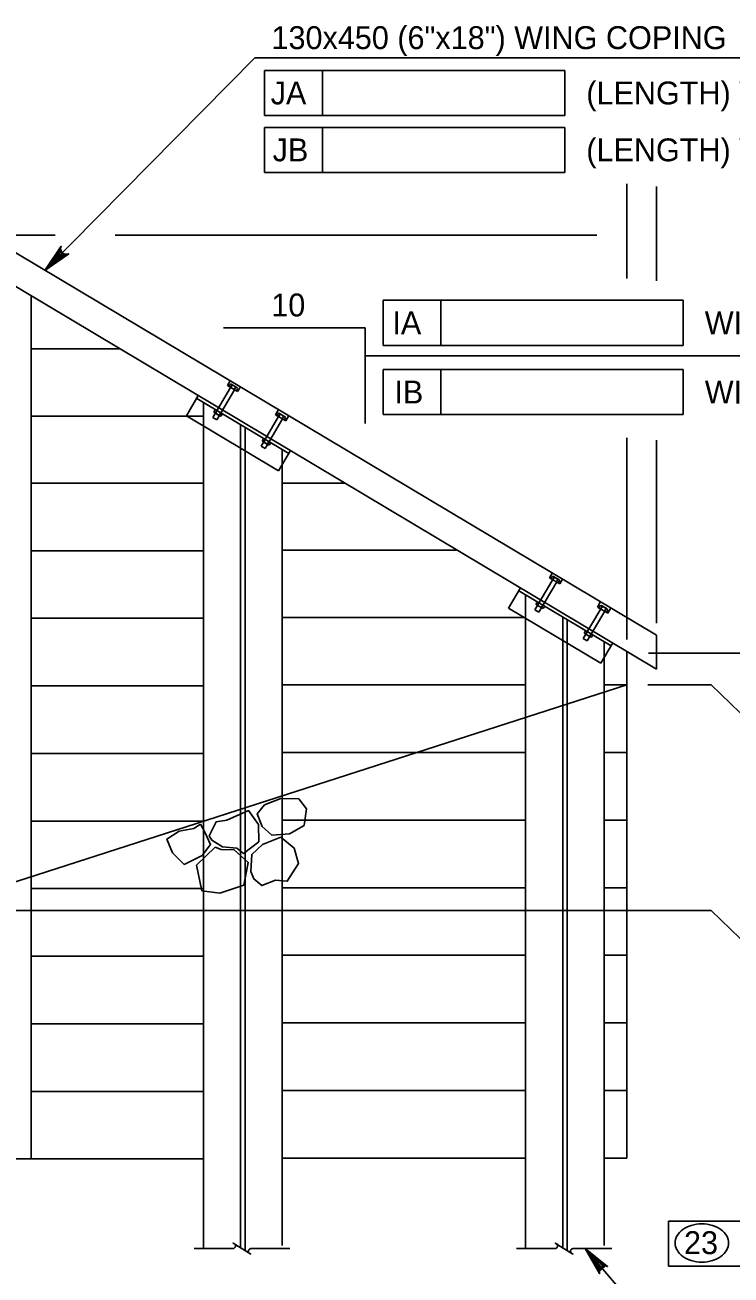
# Model space of a CAD drawing. Extents: x 635440 to 640306, y 296653 to 298484.
# Drawn here: x 639693.2 to 639785.8, y 296736.5 to 296900.4 of the extents above; entities that cross this region are included whole.
import ezdxf

# ---------------------------------------------------------------- set-up
doc = ezdxf.new("R2010")
doc.units = 0
for name, color, linetype in [('3', 7, 'Continuous'), ('4', 7, 'Continuous'), ('5', 7, 'Continuous'), ('8', 7, 'Continuous')]:
    doc.layers.add(name, color=color, linetype=linetype)

# ---------------------------------------------------------------- blocks, each defined once
blk = doc.blocks.new('ROCK')
at = {"layer": '4'}
for points in [[(2.36725, 1.088), (2.2065, 0.82625), (2.378625, 0.506625), (2.66975, 0.3095), (3.128875, 0.403375), (3.48475, 0.6775), (3.4915, 1.123375), (3.25625, 1.36725), (2.783625, 1.308375)], [(1.10175, -0.02725), (1.4015, -0.159125), (1.78825, -0.148875), (1.980875, -0.266), (2.343375, 0.09475), (2.27875, 0.5505), (1.969375, 0.883), (1.4225, 0.553625), (1.152875, 0.479), (1.0105, 0.082)], [(0.74675, 0.359875), (0.882, 0.16), (1.072875, -0.144), (0.892, -0.457375), (0.448125, -0.758625), (0.1, -0.49325), (-0.095, -0.146375), (0.202875, 0.1025), (0.579125, 0.219875)], [(2.231375, -0.71725), (2.2025, -0.266375), (2.45475, 0.037125), (2.9085, 0.28875), (3.2995, 0.047625), (3.46875, -0.344), (3.231625, -0.855), (2.92, -0.860375), (2.5765, -1.054625), (2.340375, -0.904375)], [(1.2085, -0.192875), (0.778375, -0.737625), (1.008375, -1.391375), (1.48725, -1.396875), (2.09825, -1.106625), (2.133375, -0.486375), (1.723125, -0.203375), (1.37425, -0.239875)]]:
    blk.add_lwpolyline(points, close=True, dxfattribs=at)

msp = doc.modelspace()

# ---------------------------------------------------------------- linework, layer by layer
at = {"layer": '3'}
for p, q in [((639688.15, 296872.79), (639776.08, 296820.36)), ((639688.15, 296868.36), (639776.08, 296815.93)), ((639694.03, 296788.7), (639694.03, 296864.85)), ((639705.71, 296857.89), (639694.03, 296857.89)), ((639717.86, 296848.92), (639720.18, 296852.86)), ((639719.77, 296853.1), (639720.14, 296853.72)), ((639721.12, 296852.3), (639719.77, 296853.1)), ((639719.97, 296852.98), (639720.13, 296853.25)), ((639720.36, 296853.11), (639720.2, 296852.85)), ((639720.29, 296853.27), (639721.01, 296852.85)), ((639720.84, 296852.84), (639720.68, 296852.57)), ((639720.92, 296852.42), (639721.08, 296852.69)), ((639721.12, 296852.3), (639721.49, 296852.92)), ((639714.39, 296849.14), (639715.96, 296851.78)), ((639718.39, 296848.61), (639720.71, 296852.54)), ((639718.19, 296849.96), (639718.03, 296849.68)), ((639718.09, 296849.53), (639718.81, 296849.11)), ((639718.26, 296849.55), (639718.42, 296849.82)), ((639718.73, 296849.27), (639718.89, 296849.54)), ((639719.14, 296849.4), (639718.97, 296849.13)), ((639726.07, 296849.27), (639726.44, 296849.89)), ((639726.27, 296849.15), (639726.44, 296849.43)), ((639726.59, 296849.45), (639727.31, 296849.02)), ((639714.45, 296849.1), (639694.03, 296849.1)), ((639714.39, 296849.14), (639726.49, 296841.92)), ((639716.63, 296847.8), (639716.63, 296794.57)), ((639718.39, 296848.61), (639717.86, 296848.92)), ((639724.19, 296845.15), (639726.48, 296849.03)), ((639724.72, 296844.84), (639727.01, 296848.72)), ((639727.42, 296848.48), (639726.07, 296849.27)), ((639726.66, 296849.29), (639726.5, 296849.02)), ((639727.14, 296849.01), (639726.98, 296848.74)), ((639727.22, 296848.59), (639727.38, 296848.87)), ((639727.42, 296848.48), (639727.79, 296849.09)), ((639724.52, 296846.18), (639724.36, 296845.91)), ((639724.72, 296844.84), (639724.19, 296845.15)), ((639724.42, 296845.76), (639725.14, 296845.34)), ((639724.59, 296845.78), (639724.75, 296846.05)), ((639725.06, 296845.5), (639725.22, 296845.77)), ((639725.47, 296845.63), (639725.31, 296845.35)), ((639726.48, 296841.92), (639728.06, 296844.57)), ((639726.96, 296842.73), (639726.96, 296799.31)), ((639716.63, 296840.31), (639694.03, 296840.31)), ((639735.23, 296840.29), (639726.96, 296840.29)), ((639726.96, 296834.03), (639726.96, 296829.34)), ((639716.63, 296831.45), (639694.03, 296831.45)), ((639749.97, 296831.5), (639726.96, 296831.5)), ((639762.04, 296827.9), (639762.4, 296828.52)), ((639762.23, 296827.78), (639762.4, 296828.05)), ((639762.56, 296828.07), (639763.28, 296827.65)), ((639756.65, 296823.94), (639758.22, 296826.58)), ((639760.12, 296823.72), (639762.45, 296827.66)), ((639760.65, 296823.41), (639762.98, 296827.35)), ((639763.38, 296827.1), (639762.04, 296827.9)), ((639762.62, 296827.91), (639762.46, 296827.65)), ((639763.1, 296827.64), (639762.94, 296827.37)), ((639763.19, 296827.22), (639763.34, 296827.49)), ((639763.38, 296827.1), (639763.75, 296827.72)), ((639756.65, 296823.94), (639768.75, 296816.72)), ((639760.65, 296823.41), (639760.12, 296823.72)), ((639760.45, 296824.76), (639760.29, 296824.49)), ((639760.35, 296824.34), (639761.07, 296823.91)), ((639760.52, 296824.35), (639760.68, 296824.62)), ((639760.99, 296824.07), (639761.15, 296824.34)), ((639761.4, 296824.2), (639761.24, 296823.93)), ((639766.45, 296819.95), (639768.75, 296823.83)), ((639766.98, 296819.64), (639769.28, 296823.52)), ((639768.34, 296824.07), (639768.7, 296824.69)), ((639769.69, 296823.28), (639768.34, 296824.07)), ((639768.54, 296823.95), (639768.7, 296824.23)), ((639768.92, 296824.09), (639768.76, 296823.82)), ((639768.86, 296824.25), (639769.58, 296823.82)), ((639769.4, 296823.81), (639769.24, 296823.54)), ((639769.49, 296823.4), (639769.64, 296823.67)), ((639769.69, 296823.28), (639770.05, 296823.89)), ((639716.63, 296822.59), (639694.03, 296822.59)), ((639758.89, 296822.71), (639726.96, 296822.71)), ((639758.89, 296822.6), (639758.89, 296809.58)), ((639766.98, 296819.64), (639766.45, 296819.95)), ((639766.78, 296820.98), (639766.62, 296820.71)), ((639766.68, 296820.56), (639767.4, 296820.14)), ((639766.85, 296820.58), (639767.01, 296820.85)), ((639767.32, 296820.3), (639767.48, 296820.57)), ((639767.73, 296820.43), (639767.57, 296820.15)), ((639776.08, 296820.36), (639776.08, 296815.93)), ((639768.75, 296816.72), (639770.32, 296819.37)), ((639772.18, 296818.26), (639772.18, 296813.85)), ((639769.22, 296817.53), (639769.22, 296812.95)), ((639772.18, 296813.85), (639681.37, 296784.63)), ((639716.63, 296813.73), (639694.03, 296813.73)), ((639758.89, 296813.85), (639726.96, 296813.85)), ((639772.18, 296813.85), (639769.22, 296813.85)), ((639772.18, 296813.85), (639772.18, 296751.84)), ((639769.22, 296813.02), (639769.22, 296740.39)), ((639758.89, 296809.58), (639758.89, 296740.11)), ((639716.63, 296804.87), (639694.03, 296804.87)), ((639744.65, 296804.99), (639726.96, 296804.99)), ((639758.89, 296804.99), (639744.65, 296804.99)), ((639772.18, 296804.99), (639769.22, 296804.99)), ((639726.96, 296799.31), (639726.96, 296740.39)), ((639716.63, 296796.02), (639694.03, 296796.02)), ((639758.89, 296796.14), (639726.96, 296796.14)), ((639772.18, 296796.14), (639769.22, 296796.14)), ((639716.63, 296794.57), (639716.63, 296740.11)), ((639694.03, 296751.72), (639694.03, 296788.7)), ((639716.63, 296787.16), (639694.03, 296787.16)), ((639758.89, 296787.28), (639726.96, 296787.28)), ((639772.18, 296787.28), (639769.22, 296787.28)), ((639716.63, 296778.3), (639694.03, 296778.3)), ((639758.89, 296778.42), (639726.96, 296778.42)), ((639772.18, 296778.42), (639769.22, 296778.42)), ((639716.63, 296769.44), (639694.03, 296769.44)), ((639758.89, 296769.56), (639726.96, 296769.56)), ((639772.18, 296769.56), (639769.22, 296769.56)), ((639716.63, 296760.58), (639694.03, 296760.58)), ((639758.89, 296760.7), (639726.96, 296760.7)), ((639772.18, 296760.7), (639769.22, 296760.7)), ((639716.63, 296751.72), (639684.43, 296751.72)), ((639758.89, 296751.84), (639726.96, 296751.84)), ((639772.18, 296751.84), (639769.22, 296751.84))]:
    msp.add_line(p, q, dxfattribs=at)
for centre, radius, start, end in [((639720.23, 296853.15), 0.139, 346.8498, 131.9461), ((639720.43, 296852.68), 0.438, 20.448, 98.348), ((639720.93, 296852.72), 0.153, 61.225, 128.111), ((639720.93, 296852.72), 0.153, 350.6849, 61.225), ((639718.16, 296849.65), 0.139, 166.9183, 312.0147), ((639718.67, 296849.7), 0.438, 200.5165, 278.4165), ((639726.53, 296849.32), 0.139, 346.8498, 131.9461), ((639718.88, 296849.24), 0.153, 170.7534, 237.6394), ((639718.88, 296849.24), 0.153, 237.6394, 308.1795), ((639726.73, 296848.86), 0.438, 20.448, 98.348), ((639727.23, 296848.89), 0.153, 61.225, 128.111), ((639727.23, 296848.89), 0.153, 350.6849, 61.225), ((639724.5, 296845.88), 0.139, 166.9183, 312.0147), ((639725, 296845.93), 0.438, 200.5165, 278.4165), ((639725.21, 296845.47), 0.153, 170.7534, 237.6394), ((639725.21, 296845.47), 0.153, 237.6394, 308.1795), ((639762.49, 296827.95), 0.139, 346.8498, 131.9461), ((639762.69, 296827.48), 0.438, 20.448, 98.348), ((639763.19, 296827.52), 0.153, 61.225, 128.111), ((639763.19, 296827.52), 0.153, 350.6849, 61.225), ((639760.42, 296824.45), 0.139, 166.9183, 312.0147), ((639760.93, 296824.5), 0.438, 200.5165, 278.4165), ((639761.14, 296824.05), 0.153, 170.7534, 237.6394), ((639761.14, 296824.05), 0.153, 237.6394, 308.1795), ((639768.79, 296824.12), 0.139, 346.8498, 131.9461), ((639768.99, 296823.66), 0.438, 20.448, 98.348), ((639769.5, 296823.69), 0.153, 61.225, 128.111), ((639769.5, 296823.69), 0.153, 350.6849, 61.225), ((639766.76, 296820.68), 0.139, 166.9183, 312.0147), ((639767.26, 296820.73), 0.438, 200.5165, 278.4165), ((639767.48, 296820.27), 0.153, 170.7534, 237.6394), ((639767.48, 296820.27), 0.153, 237.6394, 308.1795)]:
    msp.add_arc(centre, radius, start, end, dxfattribs=at)
at = {"layer": '4'}
for p, q in [((639695.84, 296868.2), (639723.36, 296896.06)), ((639723.36, 296896.06), (639817.05, 296896.06)), ((639724.66, 296894.41), (639764.04, 296894.41)), ((639724.66, 296894.41), (639724.66, 296888.5)), ((639732.23, 296894.41), (639732.23, 296888.5)), ((639764.04, 296894.41), (639764.04, 296888.5)), ((639724.66, 296888.5), (639764.04, 296888.5)), ((639724.66, 296886.94), (639764.04, 296886.94)), ((639724.66, 296886.94), (639724.66, 296881.04)), ((639732.23, 296886.94), (639732.23, 296881.04)), ((639764.04, 296886.94), (639764.04, 296881.04)), ((639724.66, 296881.04), (639764.04, 296881.04)), ((639772.18, 296867.13), (639772.18, 296879.52)), ((639776.08, 296866.81), (639776.08, 296879.2)), ((639691.19, 296872.79), (639697.19, 296872.79)), ((639705.04, 296872.79), (639768.25, 296872.79)), ((639740.21, 296864.27), (639779.58, 296864.27)), ((639740.21, 296864.27), (639740.21, 296858.36)), ((639747.77, 296864.27), (639747.77, 296858.36)), ((639779.58, 296864.27), (639779.58, 296858.36)), ((639737.86, 296860.66), (639719.28, 296860.66)), ((639737.86, 296848.12), (639737.86, 296860.66)), ((639740.21, 296858.36), (639779.58, 296858.36)), ((639812.7, 296857), (639737.86, 296857)), ((639740.21, 296855.21), (639779.58, 296855.21)), ((639740.21, 296855.21), (639740.21, 296849.3)), ((639747.77, 296855.21), (639747.77, 296849.3)), ((639779.58, 296855.21), (639779.58, 296849.3)), ((639694.03, 296853.07), (639694.03, 296802.99)), ((639740.21, 296849.3), (639779.58, 296849.3)), ((639772.18, 296819.8), (639772.18, 296846.26)), ((639776.08, 296821.95), (639776.08, 296845.94)), ((639775, 296818.04), (639876.46, 296818.04)), ((639783.23, 296813.85), (639774.94, 296813.85)), ((639783.23, 296813.85), (639797.65, 296799.95)), ((639783.23, 296784.27), (639687.65, 296784.27)), ((639783.23, 296784.27), (639791.75, 296776.06)), ((639777.64, 296743.56), (639818.85, 296743.56)), ((639777.64, 296737.65), (639777.64, 296743.56)), ((639766.7, 296739.98), (639774.7, 296730.71)), ((639818.85, 296737.65), (639777.64, 296737.65))]:
    msp.add_line(p, q, dxfattribs=at)
for points in [[(639695.84, 296868.2), (639697.97, 296871.35), (639697.9, 296871), (639697.98, 296870.72), (639698.13, 296870.51), (639698.33, 296870.37), (639698.62, 296870.3), (639698.96, 296870.36), (639695.84, 296868.2), (639698.62, 296870.3), (639698.33, 296870.37), (639695.84, 296868.2), (639698.13, 296870.51), (639697.98, 296870.72), (639695.84, 296868.2), (639697.9, 296871)], [(639766.7, 296739.98), (639769.66, 296737.61), (639769.33, 296737.7), (639769.04, 296737.65), (639768.82, 296737.51), (639768.66, 296737.32), (639768.57, 296737.04), (639768.61, 296736.7), (639766.7, 296739.98), (639768.57, 296737.04), (639768.66, 296737.32), (639766.7, 296739.98), (639768.82, 296737.51), (639769.04, 296737.65), (639766.7, 296739.98), (639769.33, 296737.7)]]:
    msp.add_lwpolyline(points, dxfattribs=at)
for points in [[(639698.17, 296869.89), (639697.5, 296870.55), (639695.84, 296868.2)], [(639768.59, 296737.06), (639769.3, 296737.68), (639767.09, 296739.52)]]:
    msp.add_lwpolyline(points, close=True, dxfattribs=at)
for centre, radius, start, end in [((639781.67, 296739.51), 3.66, 106.5358, 125.6316), ((639782.02, 296738.35), 4.87, 90, 106.5358), ((639782.02, 296738.35), 4.87, 73.4642, 90), ((639782.36, 296739.51), 3.66, 54.3684, 73.4642), ((639780.34, 296740.71), 1.83, 149.9767, 180), ((639781.15, 296740.25), 2.76, 125.6316, 149.9767), ((639782.89, 296740.25), 2.76, 30.0233, 54.3684), ((639783.69, 296740.71), 1.83, 0, 30.0233), ((639780.34, 296740.71), 1.83, 180, 210.0233), ((639781.15, 296741.18), 2.76, 210.0233, 234.3684), ((639782.89, 296741.18), 2.76, 305.6316, 329.9767), ((639783.69, 296740.71), 1.83, 329.9767, 0), ((639781.67, 296741.91), 3.66, 234.3684, 253.4642), ((639782.02, 296743.07), 4.87, 253.4642, 270), ((639782.02, 296743.07), 4.87, 270, 286.5358), ((639782.36, 296741.91), 3.66, 286.5358, 305.6316)]:
    msp.add_arc(centre, radius, start, end, dxfattribs=at)
at = {"layer": '8'}
for p, q in [((639715.75, 296851.41), (639727.84, 296844.2)), ((639716.63, 296850.89), (639716.63, 296847.8)), ((639716.63, 296849.1), (639714.45, 296849.1)), ((639721.5, 296847.98), (639721.5, 296740.09)), ((639722.09, 296847.63), (639722.09, 296739.72)), ((639726.96, 296844.73), (639726.96, 296842.72)), ((639758.01, 296826.21), (639770.11, 296819)), ((639758.89, 296825.69), (639758.89, 296822.6)), ((639763.76, 296822.79), (639763.76, 296740.09)), ((639764.35, 296822.43), (639764.35, 296739.72)), ((639769.22, 296819.53), (639769.22, 296817.53)), ((639720.53, 296739.98), (639715.43, 296739.98)), ((639727.96, 296739.98), (639722.86, 296739.98)), ((639762.8, 296739.98), (639757.7, 296739.98)), ((639770.23, 296739.98), (639765.13, 296739.98))]:
    msp.add_line(p, q, dxfattribs=at)
for points in [[(639722.69, 296739.34), (639722.84, 296739.25), (639720.53, 296740.7), (639720.68, 296740.6)], [(639764.96, 296739.34), (639765.1, 296739.25), (639762.79, 296740.7), (639762.95, 296740.6)]]:
    msp.add_lwpolyline(points, dxfattribs=at)
for centre, start, end in [((639720.5, 296740.32), 275.3286, 57.8672), ((639722.86, 296739.63), 90, 240), ((639762.76, 296740.32), 275.3286, 57.8672), ((639765.13, 296739.63), 90, 240)]:
    msp.add_arc(centre, 0.341, start, end, dxfattribs=at)

# ---------------------------------------------------------------- block references
at = {"layer": '4', "xscale": 4.921475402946, "yscale": 4.921475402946, "rotation": -7.300632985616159}
msp.add_blockref('ROCK', (639712.39, 296794.31), dxfattribs=at)

# ---------------------------------------------------------------- texts
at = {"layer": '4'}
for s, height, p in [('JA', 3, (639725.45, 296889.95)), ('(LENGTH) WINGWALL A', 3.0001, (639766.86, 296889.95)), ('JB', 3, (639725.71, 296882.49)), ('(LENGTH) WINGWALL B', 3.0001, (639766.86, 296882.49)), ('10', 3, (639725.53, 296862.16)), ('23', 3, (639779.68, 296739.25))]:
    msp.add_text(s, height=height, dxfattribs=at).set_placement(p)
for s, p in [('IA', (639741.42, 296859.82)), ('WINGWALL A', (639782.4, 296859.81)), ('IB', (639741.68, 296850.75)), ('WINGWALL B', (639782.4, 296850.75))]:
    msp.add_text(s, height=3, rotation=359.9382, dxfattribs=at).set_placement(p)
at = {"layer": '5'}
msp.add_text('130x450 (6"x18") WING COPING', height=3.0001, dxfattribs=at).set_placement((639725.56, 296897.2))

doc.saveas('drawing.dxf')
